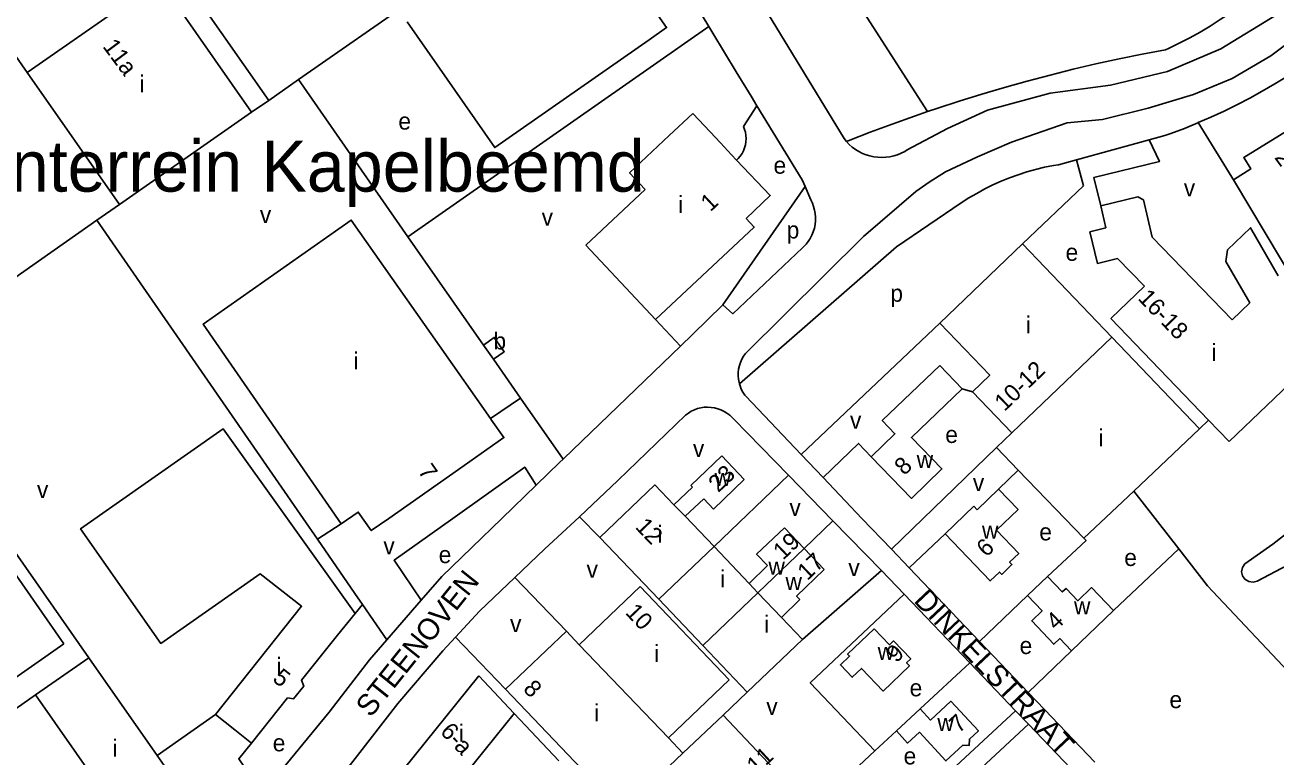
# Model space of a CAD drawing. Extents: x 156721 to 158827, y 386657 to 388950.
# Drawn here: x 157336.1 to 157630, y 388137 to 388308.9 of the extents above; entities that cross this region are included whole.
import ezdxf

# ---------------------------------------------------------------- set-up
doc = ezdxf.new("R2010")
doc.units = 0
for name, color, linetype in [('BLT_Basislijn', 7, 'Continuous'), ('BLT_Bebouwing', 7, 'Continuous'), ('BLT_Centroide', 7, 'Continuous'), ('BLT_Huisnummer', 7, 'Continuous'), ('BLT_Huisnummer_reeks', 7, 'Continuous'), ('BLT_Huisnummer_zonder_bebouwing', 7, 'Continuous'), ('BLT_Onderverdeling_panden', 7, 'Continuous'), ('BLT_Plantopo', 7, 'Continuous'), ('BLT_Sport_parknaam', 7, 'Continuous'), ('BLT_Straatnaam', 7, 'Continuous')]:
    doc.layers.add(name, color=color, linetype=linetype)

msp = doc.modelspace()

# ---------------------------------------------------------------- linework, layer by layer
at = {"layer": 'BLT_Basislijn'}
for p, q in [((157475.33, 388344.1), (157496.79, 388308.52)), ((157393.36, 388291.17), (157362.65, 388335.12)), ((157400.35, 388296.04), (157433.45, 388319.09)), ((157336.63, 388297.68), (157327.6, 388310.61)), ((157426.09, 388259.14), (157496.79, 388308.52)), ((157496.79, 388308.52), (157497.73, 388306.96)), ((157497.73, 388306.96), (157503.23, 388297.85)), ((157503.23, 388297.85), (157506.69, 388292.18)), ((157393.36, 388291.17), (157400.35, 388296.04)), ((157400.35, 388296.04), (157426.09, 388259.14)), ((157389.36, 388288.41), (157393.36, 388291.17)), ((157506.69, 388292.18), (157508.08, 388289.91)), ((157508.08, 388289.91), (157504.9, 388285.05)), ((157508.08, 388289.91), (157518.74, 388272.47)), ((157543.35, 388279.52), (157552.85, 388284.58)), ((157528.54, 388282.21), (157529.12, 388281.49)), ((157583.18, 388277.23), (157600.2, 388281.87)), ((157600.2, 388281.87), (157603.92, 388282.88)), ((157578.9, 388276.06), (157583.18, 388277.23)), ((157584.79, 388271.09), (157583.18, 388277.23)), ((157500.1, 388243.13), (157519.39, 388270.95)), ((157518.74, 388272.47), (157519.39, 388270.95)), ((157519.39, 388270.95), (157520.73, 388267.82)), ((157584.79, 388271.09), (157570.48, 388257.47)), ((157353.02, 388263.01), (157358.3, 388266.69)), ((157348.76, 388260.03), (157353.02, 388263.01)), ((157353.02, 388263.01), (157401.44, 388192.98)), ((157348.76, 388260.03), (157342.19, 388255.43)), ((157426.09, 388259.14), (157443.8, 388233.71)), ((157342.19, 388255.43), (157303.53, 388228.38)), ((157484.26, 388239.68), (157490.11, 388233.45)), ((157446.15, 388230.37), (157452.55, 388221.21)), ((157556.26, 388223.43), (157558.73, 388222.72)), ((157445.48, 388216.44), (157452.55, 388221.21)), ((157452.55, 388221.21), (157462.54, 388206.89)), ((157505.43, 388221.66), (157518.49, 388207.96)), ((157475.4, 388201.88), (157491.32, 388217.24)), ((157502.63, 388216.27), (157515.49, 388203.12)), ((157612.05, 388213.99), (157614.19, 388216.08)), ((157564.39, 388209.6), (157539.68, 388185.73)), ((157462.7, 388207.04), (157462.54, 388206.89)), ((157518.49, 388207.96), (157523.61, 388202.58)), ((157497.99, 388186.35), (157515.49, 388203.12)), ((157515.49, 388203.12), (157525.92, 388192.45)), ((157523.61, 388202.58), (157532.76, 388192.98)), ((157564.84, 388199.87), (157569.49, 388204.3)), ((157456.2, 388200.77), (157448.14, 388192.98)), ((157466.35, 388193.39), (157475.4, 388201.88)), ((157607.19, 388185.82), (157596.63, 388199.42)), ((157471.18, 388188.5), (157466.35, 388193.39)), ((157401.44, 388192.98), (157404.8, 388188.13)), ((157404.8, 388188.13), (157410.42, 388191.69)), ((157519.2, 388185.88), (157525.92, 388192.45)), ((157525.92, 388192.45), (157537.36, 388180.74)), ((157532.76, 388192.98), (157539.68, 388185.73)), ((157404.8, 388188.13), (157413.62, 388175.37)), ((157552.31, 388189.4), (157543.86, 388181.35)), ((157332.16, 388187.41), (157351.14, 388160.27)), ((157539.68, 388185.73), (157543.86, 388181.35)), ((157607.19, 388185.82), (157591.85, 388171.35)), ((157613.93, 388177.14), (157607.19, 388185.82)), ((157463.31, 388166.49), (157451.22, 388179.13)), ((157518.77, 388164.58), (157537.36, 388180.74)), ((157537.36, 388180.74), (157542.69, 388175.17)), ((157543.86, 388181.35), (157545.38, 388179.75)), ((157545.38, 388179.75), (157560.38, 388164.05)), ((157661.14, 388126.92), (157613.93, 388177.14)), ((157413.62, 388175.37), (157415.41, 388172.78)), ((157413.66, 388170.64), (157415.41, 388172.78)), ((157415.41, 388172.78), (157421.13, 388164.5)), ((157429.17, 388173.77), (157421.13, 388164.5)), ((157542.69, 388175.17), (157558.08, 388159.09)), ((157571.62, 388174.85), (157560.38, 388164.05)), ((157421.13, 388164.5), (157417.02, 388159.76)), ((157434.31, 388161.86), (157437.29, 388165.12)), ((157437.29, 388165.12), (157449.03, 388152.88)), ((157560.38, 388164.05), (157571.8, 388152.08)), ((157423.73, 388149.49), (157434.31, 388161.86)), ((157581.96, 388161.87), (157571.8, 388152.08)), ((157546.43, 388148.27), (157558.08, 388159.09)), ((157558.08, 388159.09), (157568.85, 388147.83)), ((157500.11, 388146.76), (157505.82, 388152.21)), ((157410.67, 388132.79), (157423.73, 388149.49)), ((157571.8, 388152.08), (157575.61, 388148.09)), ((157367.17, 388137.33), (157380.87, 388146.96)), ((157568.85, 388147.83), (157571.9, 388144.63)), ((157587.44, 388135.73), (157575.61, 388148.09)), ((157571.9, 388144.63), (157583.51, 388132.5)), ((157535.78, 388138.4), (157540.83, 388143.09)), ((157525.96, 388129.28), (157535.78, 388138.4))]:
    msp.add_line(p, q, dxfattribs=at)
for points in [[(157552.85, 388284.58), (157562.27, 388288.83), (157576.98, 388292.83), (157591.14, 388294.71), (157604.51, 388297.91), (157617.07, 388303.26), (157630.17, 388311.28), (157641.66, 388321.7), (157668.88, 388347.46)], [(157528.54, 388282.21), (157492.16, 388341.94)], [(157671.64, 388340.75), (157649.95, 388319.83), (157637.38, 388308.07), (157628.83, 388301.66), (157619.74, 388296.31), (157610.65, 388292.57), (157599.96, 388289.36), (157589.27, 388286.69), (157580.99, 388285.88), (157567.89, 388281.34), (157559.87, 388277.87), (157552.39, 388274.39), (157548.51, 388271.92)], [(157548.16, 388288.54), (157519.84, 388332.72)], [(157623.89, 388315.15), (157623.7, 388314.99), (157621.49, 388313.3), (157619.23, 388311.68), (157616.93, 388310.12), (157614.58, 388308.63), (157612.19, 388307.21), (157609.76, 388305.85), (157607.3, 388304.57), (157604.79, 388303.36), (157604.06, 388303.02)], [(157604.06, 388303.02), (157598.61, 388302), (157593.17, 388300.9), (157587.74, 388299.72), (157582.34, 388298.46), (157576.95, 388297.12), (157571.59, 388295.71), (157566.24, 388294.22), (157560.92, 388292.65), (157555.61, 388291), (157550.34, 388289.28), (157548.16, 388288.54)], [(157634.03, 388297.66), (157629.75, 388295.03), (157626.82, 388293.33), (157623.86, 388291.69), (157620.86, 388290.13), (157617.82, 388288.63), (157614.74, 388287.21), (157611.77, 388285.93)], [(157548.16, 388288.54), (157545.09, 388287.49), (157539.86, 388285.61), (157534.67, 388283.67), (157529.5, 388281.64), (157529.12, 388281.49)], [(157504.9, 388285.05), (157505.18, 388284.36), (157505.38, 388283.66), (157505.5, 388282.93), (157505.54, 388282.2), (157505.5, 388281.46), (157505.39, 388280.73), (157505.19, 388280.02), (157504.92, 388279.34), (157504.58, 388278.69), (157504.17, 388278.08), (157503.69, 388277.52), (157503.31, 388277.14)], [(157611.77, 388285.93), (157611.64, 388285.86), (157608.5, 388284.59), (157605.33, 388283.39), (157603.92, 388282.88)], [(157641.88, 388235.96), (157620.26, 388272.14), (157611.77, 388285.93)], [(157588.85, 388266.39), (157587.24, 388273.06), (157602.65, 388276.77), (157600.2, 388281.87)], [(157529.12, 388281.49), (157529.78, 388280.8), (157530.48, 388280.18), (157531.24, 388279.62), (157532.04, 388279.14), (157532.87, 388278.72), (157533.74, 388278.37), (157534.64, 388278.1), (157535.56, 388277.9), (157536.49, 388277.79), (157537.42, 388277.75), (157538.36, 388277.8), (157539.29, 388277.92), (157540.21, 388278.12), (157541.1, 388278.4), (157541.97, 388278.76), (157542.8, 388279.18), (157543.35, 388279.52)], [(157556.1, 388267.09), (157557.9, 388268.24), (157559.73, 388269.33), (157561.61, 388270.35), (157563.52, 388271.3), (157565.47, 388272.18), (157567.45, 388272.98), (157569.46, 388273.71), (157571.5, 388274.36), (157573.55, 388274.94), (157575.63, 388275.44), (157577.73, 388275.86), (157578.9, 388276.06)], [(157505.39, 388231.73), (157533.14, 388259.17), (157545.4, 388269.78), (157548.51, 388271.92)], [(157556.1, 388267.09), (157540.9, 388256.75), (157503.96, 388224.59)], [(157520.73, 388267.82), (157521.1, 388267.05), (157521.4, 388266.24), (157521.63, 388265.41), (157521.77, 388264.56), (157521.84, 388263.71), (157521.83, 388262.84), (157521.74, 388261.99), (157521.57, 388261.14), (157521.32, 388260.32), (157521, 388259.52), (157520.6, 388258.76), (157520.14, 388258.03), (157519.61, 388257.36), (157519.01, 388256.73), (157518.77, 388256.5)], [(157518.77, 388256.5), (157502.45, 388241.04), (157500.1, 388243.13)], [(157490.11, 388233.45), (157492.9, 388236.14), (157500.1, 388243.13)], [(157551.07, 388238.84), (157518.49, 388207.96)], [(157462.7, 388207.04), (157490.11, 388233.45)], [(157505.39, 388231.73), (157504.92, 388231.07), (157504.52, 388230.37), (157504.2, 388229.63), (157503.95, 388228.86), (157503.77, 388228.07), (157503.68, 388227.27), (157503.67, 388226.47), (157503.73, 388225.66), (157503.88, 388224.87), (157503.96, 388224.59)], [(157622.7, 388182.31), (157629.32, 388186.96), (157634.31, 388190.82), (157642.5, 388197.67), (157646.14, 388201.25), (157646.9, 388202.05), (157647.01, 388202.27), (157647.07, 388202.67), (157647.05, 388203.16), (157646.82, 388203.99), (157646.38, 388205.11), (157645.33, 388207.38), (157643.61, 388210.73), (157643.03, 388212.47), (157642.81, 388214.43), (157642.74, 388216.57), (157642.88, 388219), (157643.32, 388221.44), (157644.25, 388223.63), (157646.07, 388226), (157647.28, 388227.05)], [(157503.96, 388224.59), (157504.1, 388224.09), (157504.4, 388223.34), (157504.77, 388222.62), (157505.21, 388221.95), (157505.43, 388221.66)], [(157625.61, 388178.23), (157632.73, 388182.01), (157638.07, 388186.14), (157646.54, 388193.22), (157650.41, 388197.04), (157651.86, 388198.55), (157652.8, 388200.44), (157653.1, 388202.38), (157653, 388204.12), (157652.53, 388205.88), (157651.91, 388207.46), (157650.73, 388210.01), (157649.16, 388213.06), (157648.92, 388213.78), (157648.8, 388214.87), (157648.75, 388216.49), (157648.85, 388218.29), (157649.1, 388219.72), (157649.47, 388220.58), (157650.44, 388221.84)], [(157491.32, 388217.24), (157491.96, 388217.73), (157492.65, 388218.14), (157493.38, 388218.49), (157494.13, 388218.76), (157494.91, 388218.96), (157495.7, 388219.08), (157496.5, 388219.11), (157497.3, 388219.07), (157498.1, 388218.95), (157498.88, 388218.75), (157499.63, 388218.48), (157500.35, 388218.13), (157501.04, 388217.71), (157501.68, 388217.22), (157502.26, 388216.67), (157502.63, 388216.27)], [(157534.94, 388207.47), (157531.94, 388210.59), (157523.61, 388202.58)], [(157462.54, 388206.89), (157461.8, 388206.18), (157456.2, 388200.77)], [(157456.2, 388200.77), (157453.51, 388205.05), (157436.61, 388192.98)], [(157451.22, 388179.13), (157458.2, 388185.75), (157466.35, 388193.39)], [(157436.61, 388192.98), (157422.81, 388183.14), (157429.17, 388173.77)], [(157448.14, 388192.98), (157434.03, 388179.36), (157429.17, 388173.77)], [(157584.89, 388188.32), (157585.4, 388187.78), (157576.34, 388179.37)], [(157622.7, 388182.31), (157622.15, 388181.49), (157621.96, 388180.46), (157622.19, 388179.46), (157622.74, 388178.68), (157623.62, 388178.13), (157624.65, 388177.98), (157625.61, 388178.23)], [(157437.29, 388165.12), (157442.87, 388171.22), (157451.22, 388179.13)], [(157542.69, 388175.17), (157520.6, 388154.4), (157535.78, 388138.4)], [(157417.02, 388159.76), (157407.54, 388147.44), (157393.37, 388130.27)], [(157532.76, 388121.95), (157536.57, 388117.86), (157568.85, 388147.83)], [(157571.9, 388144.63), (157549.76, 388124.11), (157550.38, 388123.44)], [(157389.33, 388140.22), (157386.33, 388136.55), (157390.06, 388131.1), (157393.37, 388130.27)]]:
    msp.add_lwpolyline(points, dxfattribs=at)
at = {"layer": 'BLT_Bebouwing'}
for p, q in [((157358.3, 388266.69), (157336.63, 388297.68)), ((157389.36, 388288.41), (157358.3, 388266.69)), ((157493.02, 388288.11), (157487.44, 388282.88)), ((157497.1, 388283.77), (157493.02, 388288.11)), ((157499.53, 388281.17), (157497.1, 388283.77)), ((157502.12, 388278.41), (157499.53, 388281.17)), ((157503.31, 388277.14), (157502.12, 388278.41)), ((157481.8, 388270.22), (157467.87, 388257.13)), ((157588.85, 388266.39), (157597.6, 388268.52)), ((157597.6, 388268.52), (157598.88, 388267.79)), ((157598.88, 388267.79), (157600.97, 388259.01)), ((157590.09, 388261.23), (157588.85, 388266.39)), ((157590.09, 388261.23), (157586.27, 388260.31)), ((157600.97, 388259.01), (157619.7, 388239.6)), ((157591.22, 388239.97), (157599.1, 388247.55)), ((157614.19, 388216.08), (157591.22, 388239.97)), ((157443.8, 388233.71), (157446.15, 388230.37)), ((157640.87, 388231.95), (157619.05, 388211.03)), ((157445.48, 388216.44), (157445.75, 388216.06)), ((157619.05, 388211.03), (157614.19, 388216.08)), ((157492.56, 388200.73), (157499.82, 388207.69)), ((157505.11, 388202.11), (157499.82, 388207.69)), ((157492.95, 388200.33), (157488.58, 388196.18)), ((157492.56, 388200.73), (157492.95, 388200.33)), ((157497.88, 388195.16), (157505.11, 388202.11)), ((157495.59, 388197.56), (157491.19, 388193.49)), ((157497.88, 388195.16), (157495.59, 388197.56)), ((157497.99, 388186.35), (157491.19, 388193.49)), ((157519.2, 388185.88), (157514.52, 388190.79)), ((157485.01, 388174.01), (157471.18, 388188.5)), ((157506.26, 388177.71), (157497.99, 388186.35)), ((157519.2, 388185.88), (157523.9, 388180.95)), ((157345.25, 388163.53), (157331.5, 388183.23)), ((157510.55, 388181.93), (157506.26, 388177.71)), ((157495.39, 388163.15), (157485.01, 388174.01)), ((157518.18, 388173.9), (157513.83, 388169.75)), ((157581.96, 388161.87), (157591.85, 388171.35)), ((157505.82, 388152.21), (157518.77, 388164.58)), ((157505.82, 388152.21), (157495.39, 388163.15)), ((157338.61, 388151.54), (157351.14, 388160.27)), ((157367.17, 388137.33), (157351.14, 388160.27)), ((157442.77, 388156.02), (157451.07, 388147.19)), ((157307.54, 388129.89), (157338.61, 388151.54)), ((157451.07, 388147.19), (157461.56, 388136.03)), ((157375.03, 388126.08), (157367.17, 388137.33))]:
    msp.add_line(p, q, dxfattribs=at)
for points in [[(157425.93, 388309.64), (157446.49, 388280.09), (157482.75, 388305.38), (157486.85, 388308.24), (157475.11, 388325.14), (157477.04, 388326.43), (157469.71, 388338.68), (157466.83, 388336.98), (157466.26, 388337.78)], [(157336.63, 388297.68), (157367.7, 388319.4), (157389.36, 388288.41)], [(157487.44, 388282.88), (157478.14, 388274.17), (157481.8, 388270.22)], [(157505.55, 388263.4), (157511.21, 388268.79), (157503.31, 388277.14)], [(157410.42, 388191.69), (157377.98, 388238.62), (157412.77, 388263.04), (157433.52, 388233.55), (157445.48, 388216.44)], [(157484.26, 388239.68), (157507.43, 388261.4), (157505.55, 388263.4)], [(157619.7, 388239.6), (157623.86, 388243.58), (157618.26, 388253.34), (157618.65, 388256.07), (157624.07, 388261.26), (157630.53, 388249.98)], [(157599.1, 388247.55), (157592.8, 388254), (157588.07, 388252.86), (157586.27, 388260.31)], [(157467.87, 388257.13), (157484.26, 388239.68)], [(157551.07, 388238.84), (157570.48, 388257.47)], [(157570.48, 388257.47), (157591.46, 388235.52)], [(157558.73, 388222.72), (157562.77, 388226.6), (157551.07, 388238.84)], [(157446.15, 388230.37), (157448.69, 388232.12), (157446.34, 388235.49), (157443.8, 388233.71)], [(157591.46, 388235.52), (157612.05, 388213.99)], [(157551.02, 388228.91), (157537.54, 388215.97), (157540.5, 388212.86), (157534.94, 388207.47)], [(157556.26, 388223.43), (157551.02, 388228.91)], [(157534.94, 388207.47), (157544.36, 388197.67), (157551.55, 388204.59), (157544.38, 388212.02), (157556.26, 388223.43)], [(157567.99, 388213.07), (157558.73, 388222.72)], [(157380.87, 388146.96), (157401.1, 388172.34), (157391.36, 388179.96), (157367.99, 388163.61), (157349.15, 388190.54), (157382.69, 388213.99), (157413.66, 388170.64)], [(157445.75, 388216.06), (157448.62, 388211.96), (157437.92, 388204.48), (157421.57, 388192.98)], [(157612.05, 388213.99), (157596.63, 388199.42)], [(157564.39, 388209.6), (157567.99, 388213.07)], [(157569.49, 388204.3), (157564.39, 388209.6)], [(157584.89, 388188.32), (157569.49, 388204.3)], [(157471.18, 388188.5), (157484.12, 388200.84), (157488.58, 388196.18)], [(157559.8, 388195.02), (157564.84, 388199.87)], [(157564.84, 388199.87), (157569.42, 388195.07), (157564.35, 388190.24)], [(157596.63, 388199.42), (157584.89, 388188.32)], [(157421.57, 388192.98), (157417.47, 388190.11), (157414.41, 388194.48), (157410.42, 388191.69)], [(157552.31, 388189.4), (157559.04, 388195.82)], [(157559.04, 388195.82), (157559.8, 388195.02)], [(157510.55, 388181.93), (157508.01, 388184.57), (157514.52, 388190.79)], [(157564.35, 388190.24), (157569.6, 388184.73), (157567.45, 388182.7), (157567.99, 388182.14), (157565.58, 388179.83), (157565.05, 388180.39), (157562.86, 388178.32), (157552.31, 388189.4)], [(157518.18, 388173.9), (157517.39, 388174.73), (157523.9, 388180.95)], [(157571.62, 388174.85), (157576.34, 388179.37)], [(157576.34, 388179.37), (157579.83, 388175.72), (157580.71, 388176.56), (157583.49, 388173.65), (157586.7, 388176.72), (157591.85, 388171.35)], [(157466.32, 388163.33), (157480.68, 388177.02)], [(157480.68, 388177.02), (157501.59, 388155.08)], [(157581.96, 388161.87), (157579.23, 388164.77), (157577.82, 388163.44), (157572.66, 388168.92), (157575.08, 388171.24), (157571.62, 388174.85)], [(157413.66, 388170.64), (157409.55, 388165.6), (157401.07, 388154.96), (157401.61, 388153.62), (157399.22, 388150.63), (157397.8, 388150.86), (157389.33, 388140.22)], [(157518.77, 388164.58), (157513.83, 388169.75)], [(157449.03, 388152.88), (157463.31, 388166.49)], [(157463.31, 388166.49), (157466.32, 388163.33)], [(157306.95, 388138.91), (157307.95, 388137.49), (157345.25, 388163.53)], [(157433.27, 388125.13), (157424.93, 388133.96), (157442.77, 388156.02)], [(157480.99, 388128.74), (157476.49, 388133.46), (157471.79, 388128.99), (157449.03, 388152.88)], [(157501.59, 388155.08), (157487.32, 388141.42)], [(157546.43, 388148.27), (157548.88, 388145.62), (157553.67, 388150.06), (157560.11, 388143.09), (157558.01, 388141.14), (157557.94, 388139.62), (157556.46, 388139.71), (157552.48, 388136.03), (157546.24, 388142.77), (157543.48, 388140.22), (157540.83, 388143.09)], [(157389.33, 388140.22), (157385.42, 388143.34), (157380.87, 388146.96)], [(157490.68, 388137.81), (157500.11, 388146.76)], [(157500.11, 388146.76), (157518.7, 388127.15)], [(157540.83, 388143.09), (157546.43, 388148.27)], [(157487.32, 388141.42), (157490.68, 388137.81)]]:
    msp.add_lwpolyline(points, dxfattribs=at)
msp.add_lwpolyline([(157535.59, 388167.08), (157539.21, 388163.31), (157540.15, 388164.21), (157544.2, 388159.99), (157543.24, 388159.08), (157543.92, 388158.37), (157537.77, 388152.44), (157532.62, 388157.77), (157530.46, 388155.68), (157527.68, 388158.56), (157529.84, 388160.64), (157529.39, 388161.11)], close=True, dxfattribs=at)
at = {"layer": 'BLT_Onderverdeling_panden'}
for p, q in [((157591.46, 388235.52), (157567.99, 388213.07)), ((157488.58, 388196.18), (157491.19, 388193.49)), ((157485.01, 388174.01), (157497.99, 388186.35)), ((157508.32, 388175.47), (157519.2, 388185.88)), ((157506.26, 388177.71), (157508.32, 388175.47)), ((157495.39, 388163.15), (157508.32, 388175.47)), ((157508.32, 388175.47), (157513.83, 388169.75)), ((157466.32, 388163.33), (157487.32, 388141.42)), ((157433.27, 388125.13), (157451.07, 388147.19)), ((157480.99, 388128.74), (157490.68, 388137.81))]:
    msp.add_line(p, q, dxfattribs=at)
msp.add_lwpolyline([(157338.61, 388151.54), (157362.4, 388117.47), (157352.88, 388110.9), (157356.43, 388106.06)], dxfattribs=at)
at = {"layer": 'BLT_Plantopo'}
msp.add_lwpolyline([(157620.02, 388272.54), (157624.12, 388275.07), (157622.45, 388277.76), (157634.53, 388285.21), (157642.74, 388271.91), (157643.93, 388272.82), (157657.6, 388254.89), (157643.09, 388243.83), (157642.38, 388244.67), (157638.58, 388241.48)], dxfattribs=at)

# ---------------------------------------------------------------- texts
at = {"layer": 'BLT_Centroide'}
for s, p in [('i', (157363, 388293.03)), ('e', (157423.83, 388284.3)), ('e', (157511.98, 388273.93)), ('v', (157608.37, 388268.63)), ('i', (157489.53, 388264.73)), ('v', (157391.29, 388262.36)), ('v', (157457.5, 388261.75)), ('p', (157515.06, 388258.73)), ('e', (157580.59, 388253.49)), ('p', (157539.42, 388243.87)), ('i', (157571.27, 388236.44)), ('b', (157446.16, 388232.66)), ('i', (157413.3, 388227.98)), ('i', (157614.86, 388229.98)), ('v', (157529.94, 388214.04)), ('i', (157588.33, 388209.91)), ('e', (157552.33, 388210.7)), ('v', (157493.04, 388207.42)), ('w', (157545.61, 388204.81)), ('w', (157498.11, 388200.59)), ('v', (157558.81, 388199.39)), ('v', (157338.92, 388197.78)), ('v', (157515.71, 388193.57)), ('i', (157484.73, 388187.27)), ('w', (157560.95, 388188.22)), ('e', (157574.42, 388187.82)), ('v', (157420.31, 388184.56)), ('e', (157433.31, 388182.48)), ('e', (157594.38, 388181.81)), ('v', (157468.05, 388179.03)), ('w', (157510.78, 388179.74)), ('v', (157529.56, 388179.43)), ('i', (157499.47, 388176.81)), ('w', (157514.79, 388176.16)), ('w', (157582.57, 388170.44)), ('i', (157509.8, 388166.16)), ('v', (157450.07, 388166.27)), ('e', (157569.79, 388161.13)), ('i', (157483.95, 388159.27)), ('w', (157536.44, 388159.75)), ('i', (157395.2, 388156.27)), ('e', (157543.95, 388151.2)), ('i', (157469.86, 388145.33)), ('v', (157510.28, 388146.83)), ('e', (157605, 388148.42)), ('i', (157438, 388140.56)), ('w', (157550.47, 388143.03)), ('i', (157356.64, 388137.03)), ('e', (157394.31, 388138.28)), ('e', (157542.54, 388135.2))]:
    msp.add_text(s, height=4, dxfattribs=at).set_placement(p)
at = {"layer": 'BLT_Huisnummer'}
for s, rotation, p in [('1', 43.1562, (157497.15, 388264.86)), ('7', 304.9606, (157428.32, 388204.03)), ('23', 43.8693, (157499, 388198.9)), ('8', 43.8656, (157542.71, 388202.91)), ('12', 313.6694, (157479.29, 388190.83)), ('19', 43.7308, (157514.21, 388183.03)), ('6', 43.2915, (157561.97, 388183.73)), ('17', 43.7214, (157519.91, 388178.22)), ('10', 313.6142, (157476.94, 388170.73)), ('4', 43.2915, (157578.32, 388166.52)), ('9', 43.6251, (157540.82, 388158.89)), ('5', 321.431, (157394.05, 388154.95)), ('8', 313.6149, (157452.95, 388152.74)), ('7', 42.7884, (157555.53, 388142.39)), ('11', 42.7189, (157507.93, 388132.72))]:
    msp.add_text(s, height=4, rotation=rotation, dxfattribs=at).set_placement(p)
at = {"layer": 'BLT_Huisnummer_reeks'}
for s, rotation, p in [('11a', 306.5465, (157354.21, 388303.8)), ('16-18', 313.8874, (157597.4, 388244.52)), ('10-12', 43.7263, (157566.24, 388217.97)), ('6-a', 313.3762, (157433.46, 388142.73))]:
    msp.add_text(s, height=4, rotation=rotation, dxfattribs=at).set_placement(p)
at = {"layer": 'BLT_Huisnummer_zonder_bebouwing'}
msp.add_text('20', height=4, rotation=306.3422, dxfattribs=at).set_placement((157629.54, 388277.7))
at = {"layer": 'BLT_Sport_parknaam'}
msp.add_text('Bedrijventerrein Kapelbeemd', height=12, dxfattribs=at).set_placement((157274.77, 388269.73))
at = {"layer": 'BLT_Straatnaam'}
for s, rotation, p in [('STEENOVEN', 51.3018, (157417.33, 388146.02)), ('DINKELSTRAAT', 313.4118, (157544.7, 388173.53))]:
    msp.add_text(s, height=5, rotation=rotation, dxfattribs=at).set_placement(p)

doc.saveas('drawing.dxf')
